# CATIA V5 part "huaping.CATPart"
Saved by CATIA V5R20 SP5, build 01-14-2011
Part number: Part2
Material "Eroded metal 2": density 7860 kg/m3, Young's modulus 2e+11 Pa, Poisson ratio 0.266
Bounding box of the stored display mesh (mm): x -60 to 60, y -60.538 to 59.939, z 0 to 146.924
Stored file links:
  E:\huaping.CATPart
  C:\Program Files\Dassault Systemes\B20\intel_a\startup\materials\Catalog.CATMaterial
  C:\Program Files\Dassault Systemes\B20\intel_a\startup\materials\eroded_metal_2.jpg
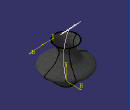
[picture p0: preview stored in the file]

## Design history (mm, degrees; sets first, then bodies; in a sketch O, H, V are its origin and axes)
Set1
  Plane1: type Offset, RefPlane xy-plane, Offset 20
  Plane2: type Offset, RefPlane Plane1, Offset 20
  Plane3: type Offset, RefPlane Plane2, Offset 20
  Plane4: type Offset, RefPlane Plane3, Offset 20
  Plane5: type Offset, RefPlane Plane4, Offset 20
  Sketch1 on xy-plane, origin (0, 0, 0), H (1, 0, 0), V (0, 1, 0)
    circle A1 centre (0, 0) radius 20
    point P1 (20, 0)
    coincidence: A1 P1, P1 H
  Sketch2 on Plane1, origin (0, 0, 20), H (1, 0, 0), V (0, 1, 0)
    circle A1 centre (0, 0) radius 40
  Sketch3 on Plane2, origin (0, 0, 40), H (1, 0, 0), V (0, 1, 0)
    circle A1 centre (0, 0) radius 60
    point P1 (60, 0)
    coincidence: A1 P1, P1 H
  Sketch4 on Plane3, origin (0, 0, 60), H (1, 0, 0), V (0, 1, 0)
    circle A1 centre (0, 0) radius 30
    point P1 (30, 0)
    coincidence: A1 P1, P1 H
  Sketch5 on Plane4, origin (0, 0, 80), H (1, 0, 0), V (0, 1, 0)
    circle A1 centre (0, 0) radius 20
    point P1 (20, 0)
    coincidence: A1 P1, P1 H
  Sketch6 on Plane5, origin (0, 0, 100), H (1, 0, 0), V (0, 1, 0)
    circle A1 centre (0.7126, 0) radius 30
    point P1 (0.7126, 0)
    point P2 (30.7126, 0)
    coincidence: P1 H, A1 P2, P2 H
Body1 (main body), material "Eroded metal 2"
  Loft1: solid, Sections (Sketch1; Sketch2; Sketch3; Sketch4; Sketch5; Sketch6)
  Shell1: ExtOffset 0, Face face of Loft1, IntOffset 1
  Sketch7 on yz-plane, origin (0, 0, 0), H (0, 1, 0), V (0, 0, 1)
    spline S1 through (0, 0) (-7.3859, 50.1458) (8.439, 129.9573)
    point P1 (0, 0)
    coincidence: P1 O
  Plane6: type Tangent, Support face of Loft1, RefPoint vertex of Sketch7
  Sketch8 on Plane6, origin (5.11, -60.5377, 60.46), H (0.9965, 0.0841, 0), V (-0.0593, 0.7029, 0.7088)
    circle A1 centre (0, 98.0817) radius 14.8538
    point P1 (0, 98.0817)
    arc A2 centre (14.0315, 108.8562) radius 7.7174 from (6.7207, 111.3282) to (14.5324, 101.1551) cw
    point P3 (6.7207, 111.3282)
    point P4 (14.5324, 101.1551)
    arc A3 centre (16.2884, 94.5025) radius 6.8805 from (14.5324, 101.1551) to (11.9051, 89.1989) cw
    point P6 (11.9051, 89.1989)
    arc A4 centre (-0.9949, 113.937) radius 8.1447 from (6.7207, 111.3282) to (-8.3238, 110.3842) ccw
    point P8 (-8.3238, 110.3842)
    arc A5 centre (-15.5723, 108.5576) radius 7.4751 from (-8.3238, 110.3842) to (-14.5324, 101.1551) ccw
    point P10 (-14.5324, 101.1551)
    arc A6 centre (-13.4527, 93.4697) radius 7.7609 from (-14.5324, 101.1551) to (-9.5899, 86.7384) ccw
    point P12 (-9.5899, 86.7384)
    arc A7 centre (-3.3434, 82.2071) radius 7.7169 from (-9.5899, 86.7384) to (4.2, 83.834) ccw
    point P14 (4.2, 83.834)
    arc A8 centre (9.7418, 84.0904) radius 5.5477 from (4.2, 83.834) to (11.9051, 89.1989) ccw
    coincidence: P1 V, P3 A1, P4 A1, P6 A1, P8 A1, P10 A1, P12 A1, P14 A1
    tangency: A4 A2, A6 A5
